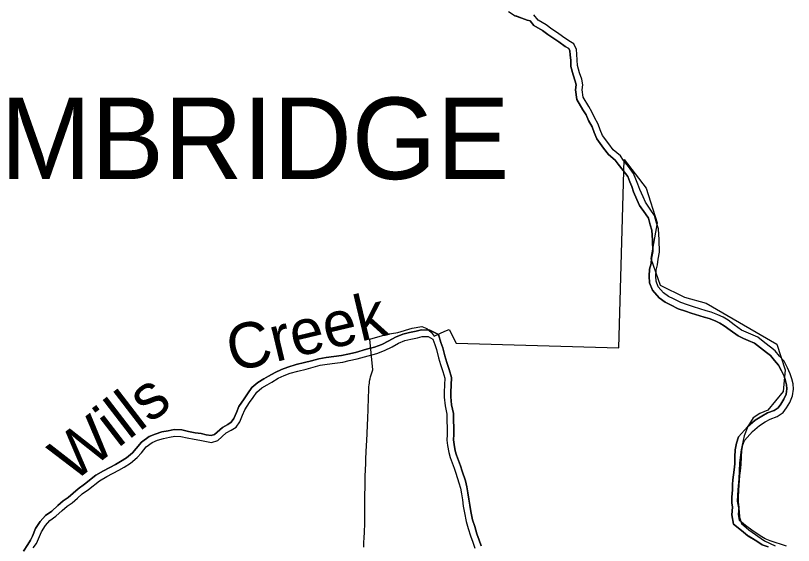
# Model space of a CAD drawing. Extents: x -29.6 to 34, y 0 to 22.
# Drawn here: x -25.281 to -23.758, y 4.576 to 5.614 of the extents above; entities that cross this region are included whole.
import ezdxf

# ---------------------------------------------------------------- set-up
doc = ezdxf.new("R2010")
doc.units = 0
for name, color, linetype in [('GM_X_Corporation', 7, 'Continuous'), ('GM_X_Major_River', 7, 'Continuous'), ('GM_X_Major_River_Text', 7, 'Continuous'), ('GM_X_Township_Text', 7, 'Continuous')]:
    doc.layers.add(name, color=color, linetype=linetype)

msp = doc.modelspace()

# ---------------------------------------------------------------- linework, layer by layer
at = {"layer": 'GM_X_Corporation'}
msp.add_lwpolyline([(-24.5992, 4.5728), (-24.5989, 4.5818), (-24.5986, 4.5909), (-24.5982, 4.602), (-24.5975, 4.6192), (-24.5972, 4.6277), (-24.5971, 4.6354), (-24.5972, 4.6442), (-24.5971, 4.6588), (-24.597, 4.6767), (-24.5969, 4.6887), (-24.5968, 4.7021), (-24.5966, 4.7077), (-24.5965, 4.7127), (-24.596, 4.7237), (-24.5955, 4.737), (-24.5951, 4.7458), (-24.5937, 4.7724), (-24.5933, 4.7811), (-24.5926, 4.7962), (-24.5912, 4.8258), (-24.5906, 4.842), (-24.5898, 4.8665), (-24.5895, 4.8796), (-24.5891, 4.8867), (-24.5888, 4.8908), (-24.5884, 4.8941), (-24.588, 4.8971), (-24.5874, 4.9003), (-24.587, 4.9028), (-24.586, 4.9067), (-24.5851, 4.9105), (-24.5844, 4.9125), (-24.5837, 4.9146), (-24.5829, 4.9164), (-24.5821, 4.9184), (-24.5813, 4.92), (-24.5874, 4.9802), (-24.5535, 4.9902), (-24.5329, 4.9933), (-24.5044, 5.002), (-24.4854, 5.0052), (-24.4759, 5.0013), (-24.4673, 4.9939), (-24.4614, 4.9863), (-24.4405, 4.9957), (-24.4319, 4.9995), (-24.4183, 4.9727), (-24.0995, 4.9634), (-24.0889, 5.3325), (-24.046, 5.2759), (-24.0248, 5.2082), (-24.0368, 5.1382), (-24.0189, 5.0861), (-23.9712, 5.0624), (-23.9284, 5.0505), (-23.79, 4.9707), (-23.7741, 4.9199), (-23.7774, 4.8776), (-23.8075, 4.841), (-23.8232, 4.8347), (-23.8365, 4.8261), (-23.8467, 4.8088), (-23.8538, 4.7908), (-23.86, 4.7633), (-23.8632, 4.7382), (-23.8647, 4.7068), (-23.8663, 4.6849), (-23.8679, 4.6629), (-23.8639, 4.6433), (-23.8631, 4.6316), (-23.8592, 4.619), (-23.8451, 4.6065), (-23.8145, 4.5853), (-23.7934, 4.5751)], dxfattribs=at)
at = {"layer": 'GM_X_Major_River'}
for points in [[(-24.3156, 5.6222), (-24.3026, 5.6141)], [(-24.3026, 5.6141), (-24.2899, 5.6094), (-24.2791, 5.6056), (-24.2733, 5.6044), (-24.2661, 5.5952), (-24.249, 5.5852), (-24.2386, 5.5774), (-24.2273, 5.5698), (-24.2172, 5.5629), (-24.2046, 5.5538), (-24.1977, 5.5499), (-24.1955, 5.5451), (-24.1952, 5.5377), (-24.194, 5.5262), (-24.1939, 5.5147), (-24.1893, 5.4983), (-24.1849, 5.4862), (-24.1835, 5.4785), (-24.1845, 5.4688), (-24.1821, 5.4501), (-24.1699, 5.4297), (-24.1639, 5.4198), (-24.1593, 5.409), (-24.152, 5.3962), (-24.1482, 5.3856), (-24.1428, 5.3729), (-24.1297, 5.3549), (-24.1201, 5.3424), (-24.1066, 5.331), (-24.1012, 5.3229), (-24.0912, 5.3105), (-24.0822, 5.2988), (-24.0784, 5.2886), (-24.0745, 5.2796), (-24.0709, 5.2689), (-24.0641, 5.2537), (-24.0589, 5.2424), (-24.0476, 5.2259), (-24.0417, 5.2173), (-24.0385, 5.2044), (-24.0349, 5.1941), (-24.0335, 5.1746), (-24.0333, 5.152), (-24.0356, 5.1387), (-24.0365, 5.1283), (-24.0393, 5.1175), (-24.0405, 5.1037), (-24.0394, 5.0906), (-24.0335, 5.0761), (-24.0208, 5.0614), (-24.0092, 5.0528), (-23.9985, 5.0474), (-23.9831, 5.04), (-23.9693, 5.0353), (-23.9577, 5.031), (-23.9325, 5.0236), (-23.923, 5.0206), (-23.9107, 5.016), (-23.9015, 5.0116), (-23.8931, 5.0067), (-23.8817, 4.9979), (-23.866, 4.9869), (-23.8556, 4.9818), (-23.8464, 4.9778), (-23.8341, 4.9725), (-23.8219, 4.963), (-23.8105, 4.9542), (-23.8026, 4.948), (-23.7946, 4.9387), (-23.7869, 4.9296), (-23.781, 4.9185), (-23.776, 4.9075), (-23.7731, 4.8986), (-23.771, 4.8907), (-23.7707, 4.8826), (-23.772, 4.8723), (-23.7761, 4.8626), (-23.7824, 4.8529), (-23.7872, 4.8458), (-23.7954, 4.8403), (-23.8082, 4.8358), (-23.8195, 4.8296), (-23.8323, 4.8213), (-23.8473, 4.8084), (-23.8651, 4.7886), (-23.8694, 4.7763), (-23.8718, 4.7632), (-23.8721, 4.7495), (-23.8727, 4.7359), (-23.874, 4.724), (-23.8753, 4.7142), (-23.876, 4.7045), (-23.8767, 4.6952), (-23.8773, 4.6852), (-23.8783, 4.6706), (-23.8782, 4.6597), (-23.8772, 4.6511), (-23.8785, 4.6357), (-23.8751, 4.618), (-23.8596, 4.605), (-23.8468, 4.595)], [(-23.8473, 4.5954), (-23.8596, 4.605), (-23.8751, 4.618), (-23.8785, 4.6357), (-23.8772, 4.6511), (-23.8782, 4.6597), (-23.8783, 4.6706), (-23.8773, 4.6852), (-23.8767, 4.6952), (-23.876, 4.7045), (-23.8753, 4.7142), (-23.874, 4.724), (-23.8727, 4.7359), (-23.8721, 4.7495), (-23.8718, 4.7632), (-23.8694, 4.7763), (-23.8651, 4.7886), (-23.8473, 4.8084), (-23.8323, 4.8213), (-23.8195, 4.8296), (-23.8082, 4.8358), (-23.7954, 4.8403), (-23.7872, 4.8458), (-23.7824, 4.8529), (-23.7761, 4.8626), (-23.772, 4.8723), (-23.7707, 4.8826), (-23.771, 4.8907), (-23.7731, 4.8986), (-23.776, 4.9075), (-23.781, 4.9185), (-23.7869, 4.9296), (-23.7946, 4.9387), (-23.8026, 4.948), (-23.8105, 4.9542), (-23.8219, 4.963), (-23.8341, 4.9725), (-23.8464, 4.9778), (-23.8556, 4.9818), (-23.866, 4.9869), (-23.8817, 4.9979), (-23.8931, 5.0067), (-23.9015, 5.0116), (-23.9107, 5.016), (-23.923, 5.0206), (-23.9325, 5.0236), (-23.9577, 5.031), (-23.9693, 5.0353), (-23.9831, 5.04), (-23.9985, 5.0474), (-24.0092, 5.0528), (-24.0208, 5.0614), (-24.0335, 5.0761), (-24.0394, 5.0906), (-24.0405, 5.1037), (-24.0393, 5.1175), (-24.0365, 5.1283), (-24.0356, 5.1387), (-24.0333, 5.152), (-24.0335, 5.1746), (-24.0349, 5.1941), (-24.0385, 5.2044), (-24.0417, 5.2173), (-24.0476, 5.2259), (-24.0589, 5.2424), (-24.0641, 5.2537), (-24.0709, 5.2689), (-24.0745, 5.2796), (-24.0784, 5.2886), (-24.0822, 5.2988), (-24.0912, 5.3105), (-24.1012, 5.3229), (-24.1066, 5.331), (-24.1201, 5.3424), (-24.1297, 5.3549), (-24.1428, 5.3729), (-24.1482, 5.3856), (-24.152, 5.3962), (-24.1593, 5.409), (-24.1639, 5.4198), (-24.1699, 5.4297), (-24.1821, 5.4501), (-24.1845, 5.4688), (-24.1835, 5.4785), (-24.1849, 5.4862), (-24.1893, 5.4983), (-24.1939, 5.5147), (-24.194, 5.5262), (-24.1952, 5.5377), (-24.1955, 5.5451), (-24.1977, 5.5499), (-24.2046, 5.5538), (-24.2172, 5.5629), (-24.2273, 5.5698), (-24.2386, 5.5774), (-24.249, 5.5852), (-24.2661, 5.5952), (-24.2733, 5.6044), (-24.2791, 5.6056), (-24.2899, 5.6094), (-24.3013, 5.6136)], [(-23.8393, 4.6057), (-23.8514, 4.6152), (-23.8631, 4.625), (-23.8654, 4.6364), (-23.864, 4.6513), (-23.8652, 4.6606), (-23.8652, 4.6702), (-23.8643, 4.6844), (-23.8636, 4.6943), (-23.863, 4.7036), (-23.8623, 4.7128), (-23.861, 4.7224), (-23.8597, 4.7349), (-23.8591, 4.7491), (-23.8588, 4.7619), (-23.8567, 4.7729), (-23.8536, 4.7818), (-23.8381, 4.799), (-23.8244, 4.8108), (-23.8128, 4.8184), (-23.8029, 4.8238), (-23.7895, 4.8285), (-23.7778, 4.8364), (-23.7715, 4.8457), (-23.7645, 4.8564), (-23.7593, 4.8689), (-23.7576, 4.882), (-23.758, 4.8927), (-23.7606, 4.9023), (-23.7638, 4.9122), (-23.7692, 4.9242), (-23.776, 4.937), (-23.7846, 4.9472), (-23.7936, 4.9575), (-23.8025, 4.9645), (-23.8139, 4.9733), (-23.8274, 4.9839), (-23.8413, 4.9898), (-23.8501, 4.9937), (-23.8594, 4.9982), (-23.874, 5.0084), (-23.8857, 5.0176), (-23.8954, 5.0232), (-23.9057, 5.0281), (-23.9188, 5.033), (-23.9287, 5.0361), (-23.9536, 5.0434), (-23.965, 5.0476), (-23.9781, 5.0521), (-23.9927, 5.0591), (-24.0023, 5.064), (-24.0119, 5.071), (-24.0223, 5.083), (-24.0266, 5.0937), (-24.0274, 5.1036), (-24.0264, 5.1153), (-24.0236, 5.126), (-24.0226, 5.1371), (-24.0203, 5.1509), (-24.0204, 5.1751), (-24.022, 5.1968), (-24.026, 5.2081), (-24.0296, 5.2227), (-24.0368, 5.2333), (-24.0475, 5.2488), (-24.0522, 5.2591), (-24.0587, 5.2736), (-24.0623, 5.2843), (-24.0663, 5.2935), (-24.0706, 5.3052), (-24.081, 5.3186), (-24.0906, 5.3306), (-24.0967, 5.3398), (-24.1106, 5.3514), (-24.1192, 5.3628), (-24.1314, 5.3794), (-24.1361, 5.3904), (-24.14, 5.4017), (-24.1476, 5.4148), (-24.1523, 5.4258), (-24.1587, 5.4364), (-24.1695, 5.4544), (-24.1713, 5.469), (-24.1704, 5.479), (-24.1722, 5.4896), (-24.1769, 5.5024), (-24.1809, 5.5166), (-24.181, 5.5269), (-24.1821, 5.5386), (-24.1825, 5.5482), (-24.1876, 5.5592), (-24.1975, 5.5648), (-24.2097, 5.5736), (-24.22, 5.5806), (-24.231, 5.588), (-24.2417, 5.5961), (-24.2574, 5.6052), (-24.2659, 5.6162)], [(-25.2658, 4.5648), (-25.2577, 4.578), (-25.2522, 4.5863), (-25.2484, 4.5945), (-25.2421, 4.6089), (-25.233, 4.623), (-25.2229, 4.635), (-25.2106, 4.6434), (-25.1988, 4.6544), (-25.1883, 4.6632), (-25.1787, 4.67), (-25.1683, 4.6785), (-25.1589, 4.687), (-25.1462, 4.6963), (-25.1242, 4.7135), (-25.1091, 4.7224), (-25.0857, 4.7346), (-25.0756, 4.7405), (-25.0639, 4.7478), (-25.0522, 4.7577), (-25.0451, 4.7657), (-25.035, 4.7787), (-25.0199, 4.7892), (-25.0078, 4.7943), (-24.9948, 4.7984), (-24.9825, 4.8007), (-24.9706, 4.8032), (-24.9559, 4.8028), (-24.9424, 4.7995), (-24.9295, 4.7968), (-24.9181, 4.7951), (-24.908, 4.793), (-24.8981, 4.7912), (-24.8916, 4.7931), (-24.8763, 4.8073), (-24.8656, 4.8128), (-24.8588, 4.8174), (-24.8539, 4.8246), (-24.8489, 4.8366), (-24.8442, 4.848), (-24.8339, 4.8636), (-24.8268, 4.8734), (-24.8186, 4.8853), (-24.8069, 4.8955), (-24.7952, 4.9022), (-24.7857, 4.9076), (-24.7729, 4.9151), (-24.7606, 4.9209), (-24.7479, 4.9257), (-24.7316, 4.9303), (-24.7153, 4.9343), (-24.702, 4.9379), (-24.6875, 4.9418), (-24.6728, 4.9441), (-24.6579, 4.946), (-24.6429, 4.9482), (-24.6306, 4.951), (-24.6154, 4.9543), (-24.5941, 4.9604), (-24.578, 4.9646), (-24.5637, 4.97), (-24.5502, 4.9767), (-24.5371, 4.9841), (-24.5226, 4.9903), (-24.5096, 4.9932), (-24.4969, 4.9957), (-24.4863, 4.9986), (-24.47, 4.9982), (-24.4528, 4.9894), (-24.4481, 4.9738), (-24.4443, 4.9635), (-24.4406, 4.9473), (-24.4364, 4.9347), (-24.432, 4.9209), (-24.4277, 4.9053), (-24.428, 4.8902), (-24.4287, 4.8762), (-24.4289, 4.8673), (-24.4272, 4.8518), (-24.4234, 4.8345), (-24.4231, 4.7937)], [(-24.4231, 4.7935), (-24.4234, 4.8345), (-24.4272, 4.8518), (-24.4289, 4.8673), (-24.4287, 4.8762), (-24.428, 4.8902), (-24.4277, 4.9053), (-24.432, 4.9209), (-24.4364, 4.9347), (-24.4406, 4.9473), (-24.4443, 4.9635), (-24.4481, 4.9738), (-24.4528, 4.9894), (-24.47, 4.9982), (-24.4863, 4.9986), (-24.4969, 4.9957), (-24.5096, 4.9932), (-24.5226, 4.9903), (-24.5371, 4.9841), (-24.5502, 4.9767), (-24.5637, 4.97), (-24.578, 4.9646), (-24.5941, 4.9604), (-24.6154, 4.9543), (-24.6306, 4.951), (-24.6429, 4.9482), (-24.6579, 4.946), (-24.6728, 4.9441), (-24.6875, 4.9418), (-24.702, 4.9379), (-24.7153, 4.9343), (-24.7316, 4.9303), (-24.7479, 4.9257), (-24.7606, 4.9209), (-24.7729, 4.9151), (-24.7857, 4.9076), (-24.7952, 4.9022), (-24.8069, 4.8955), (-24.8186, 4.8853), (-24.8268, 4.8734), (-24.8339, 4.8636), (-24.8442, 4.848), (-24.8489, 4.8366), (-24.8539, 4.8246), (-24.8588, 4.8174), (-24.8656, 4.8128), (-24.8763, 4.8073), (-24.8916, 4.7931), (-24.8981, 4.7912), (-24.908, 4.793), (-24.9181, 4.7951), (-24.9295, 4.7968), (-24.9424, 4.7995), (-24.9559, 4.8028), (-24.9706, 4.8032), (-24.9825, 4.8007), (-24.9948, 4.7984), (-25.0078, 4.7943), (-25.0199, 4.7892), (-25.035, 4.7787), (-25.0451, 4.7657), (-25.0522, 4.7577), (-25.0639, 4.7478), (-25.0756, 4.7405), (-25.0857, 4.7346), (-25.1091, 4.7224), (-25.1242, 4.7135), (-25.1462, 4.6963), (-25.1589, 4.687), (-25.1683, 4.6785), (-25.1787, 4.67), (-25.1883, 4.6632), (-25.1988, 4.6544), (-25.2106, 4.6434), (-25.2229, 4.635), (-25.233, 4.623), (-25.2421, 4.6089), (-25.2484, 4.5945), (-25.2522, 4.5863), (-25.2577, 4.578), (-25.2658, 4.5648)], [(-25.2467, 4.571), (-25.2407, 4.5799), (-25.2365, 4.5892), (-25.2306, 4.6027), (-25.2225, 4.6152), (-25.2141, 4.6252), (-25.2025, 4.6331), (-25.1901, 4.6446), (-25.1803, 4.6528), (-25.1708, 4.6597), (-25.1598, 4.6686), (-25.1507, 4.6769), (-25.1383, 4.6858), (-25.1168, 4.7027), (-25.1027, 4.711), (-25.0794, 4.7232), (-25.0689, 4.7293), (-25.0562, 4.7372), (-25.0431, 4.7483), (-25.035, 4.7573), (-25.0259, 4.7691), (-25.0136, 4.7777), (-25.0033, 4.782), (-24.9917, 4.7857), (-24.98, 4.7879), (-24.9694, 4.7901), (-24.9577, 4.7898), (-24.9452, 4.7867), (-24.9318, 4.784), (-24.9204, 4.7823), (-24.9105, 4.7802), (-24.8974, 4.7778), (-24.885, 4.7815), (-24.8688, 4.7965), (-24.8589, 4.8016), (-24.8494, 4.808), (-24.8424, 4.8184), (-24.8368, 4.8316), (-24.8326, 4.8419), (-24.8232, 4.8562), (-24.8161, 4.8658), (-24.8088, 4.8765), (-24.7993, 4.8848), (-24.7887, 4.8909), (-24.7791, 4.8963), (-24.7668, 4.9035), (-24.7555, 4.9089), (-24.7438, 4.9133), (-24.7283, 4.9176), (-24.712, 4.9217), (-24.6986, 4.9253), (-24.6848, 4.929), (-24.671, 4.9312), (-24.6561, 4.9331), (-24.6405, 4.9353), (-24.6278, 4.9383), (-24.6122, 4.9416), (-24.5907, 4.9478), (-24.574, 4.9522), (-24.5585, 4.958), (-24.544, 4.9652), (-24.5313, 4.9724), (-24.5186, 4.9778), (-24.5069, 4.9804), (-24.4938, 4.9829), (-24.4846, 4.9855), (-24.4733, 4.9852), (-24.4637, 4.9803), (-24.4604, 4.9697), (-24.4568, 4.9598), (-24.4532, 4.9438), (-24.4488, 4.9307), (-24.4445, 4.9172), (-24.4408, 4.9037), (-24.4411, 4.8906), (-24.4417, 4.8767), (-24.442, 4.8668), (-24.4401, 4.8497), (-24.4364, 4.833), (-24.4362, 4.7936)], [(-24.4362, 4.7936), (-24.4364, 4.7826), (-24.4353, 4.7716), (-24.4327, 4.7581), (-24.4298, 4.7485), (-24.4262, 4.7382), (-24.4222, 4.7276), (-24.419, 4.7177), (-24.4128, 4.6989), (-24.4099, 4.6882), (-24.4081, 4.6769), (-24.4062, 4.6652), (-24.4047, 4.6527), (-24.4021, 4.64), (-24.3988, 4.6226), (-24.3945, 4.6095), (-24.3901, 4.5949), (-24.3858, 4.5822), (-24.3818, 4.5708)], [(-24.3696, 4.5753), (-24.3734, 4.5864), (-24.3777, 4.5989), (-24.382, 4.6134), (-24.3862, 4.6259), (-24.3893, 4.6425), (-24.3918, 4.6548), (-24.3933, 4.667), (-24.3952, 4.6789), (-24.3971, 4.691), (-24.4003, 4.7026), (-24.4066, 4.7217), (-24.4099, 4.7319), (-24.4139, 4.7427), (-24.4174, 4.7526), (-24.42, 4.7612), (-24.4224, 4.7735), (-24.4234, 4.7831), (-24.4231, 4.7935)], [(-24.4231, 4.7933), (-24.4234, 4.7831), (-24.4224, 4.7735), (-24.42, 4.7612), (-24.4174, 4.7526), (-24.4139, 4.7427), (-24.4099, 4.7319), (-24.4066, 4.7217), (-24.4003, 4.7026), (-24.3971, 4.691), (-24.3952, 4.6789), (-24.3933, 4.667), (-24.3918, 4.6548), (-24.3893, 4.6425), (-24.3862, 4.6259), (-24.382, 4.6134), (-24.3777, 4.5989), (-24.3734, 4.5864), (-24.3696, 4.5753)], [(-23.771, 4.5749), (-23.803, 4.5853), (-23.8129, 4.5892), (-23.8225, 4.5951), (-23.8393, 4.6057)], [(-23.8468, 4.595), (-23.8295, 4.5841), (-23.8188, 4.5774), (-23.8074, 4.573)], [(-23.8074, 4.573), (-23.8188, 4.5774), (-23.8295, 4.5841), (-23.8462, 4.5946)]]:
    msp.add_lwpolyline(points, dxfattribs=at)

# ---------------------------------------------------------------- texts
at = {"layer": 'GM_X_Major_River_Text'}
for s, rotation, p in [('Creek', 13.4421, (-24.856, 4.9154)), ('Wills', 37.5213, (-25.17, 4.6977))]:
    msp.add_text(s, height=0.08877, rotation=rotation, dxfattribs=at).set_placement(p)
at = {"layer": 'GM_X_Township_Text'}
msp.add_text('CAMBRIDGE', height=0.1598, rotation=0, dxfattribs=at).set_placement((-25.6082, 5.294))

doc.saveas('drawing.dxf')
